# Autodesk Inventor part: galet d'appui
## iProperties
Shininess: 64.0
Length Units: 11269
Angle Units: 11279
Time Units: 11290
Mass Units: 11283
Length Display Precision: 3
Angle Display Precision: 2
Compacted: True
Part Number: galet d'appui
Document SubType Name: Modeling
Created: 2005-02
Material: Par défaut
Designer: LEGERET Philippe
Density: 0.0
Volumn: 0.0
Area: 0.0
PropertySet Name: Model Information
Control State: 0
Master: False
Checked Out: False
Author: LEGERET Philippe
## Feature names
1. Révolution1 [Revolution]
